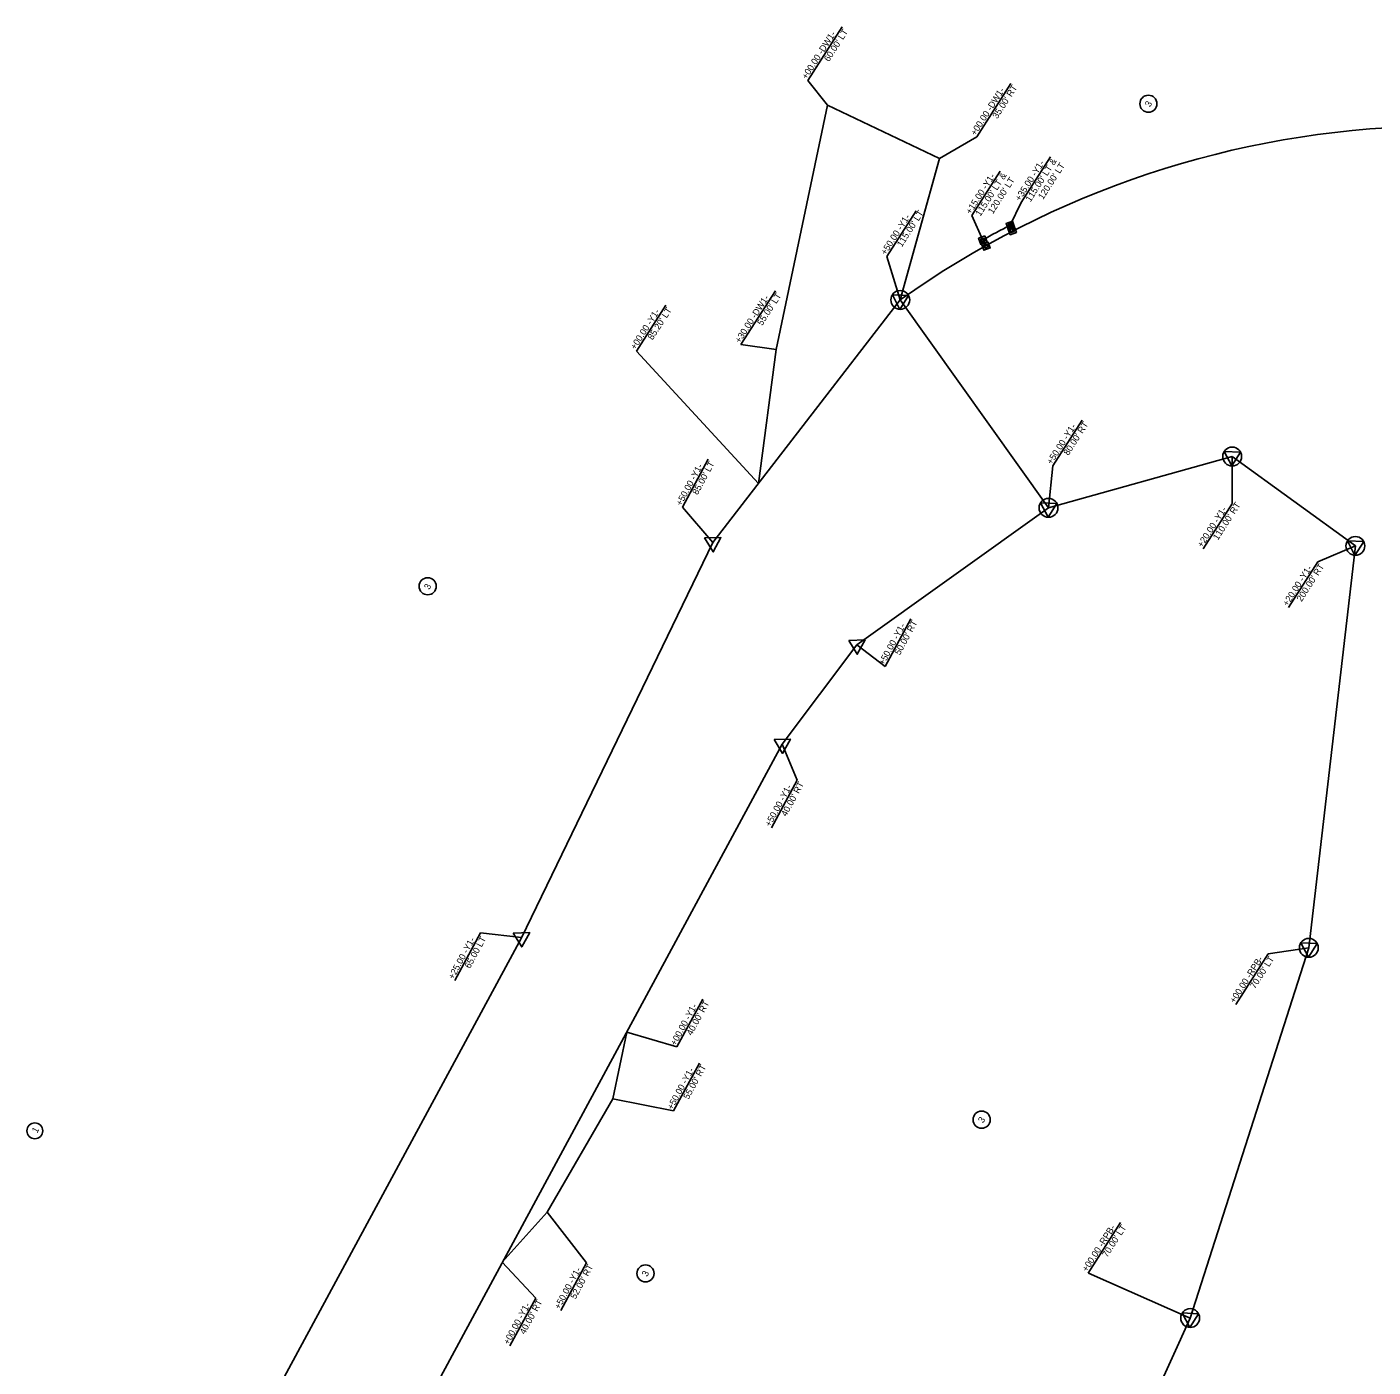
# Model space of a CAD drawing. Extents: x 2345854 to 2349056, y 842589 to 845145.
# Drawn here: x 2346489 to 2347518, y 843495 to 844519 of the extents above; entities that cross this region are included whole.
import ezdxf

# ---------------------------------------------------------------- set-up
doc = ezdxf.new("R2010")
doc.units = 0
for name, color, linetype in [('Prop Easement Construction', 7, 'Continuous'), ('Prop Easement Construction Station Offsets', 7, 'Continuous'), ('Prop Easement Permanent Drainage', 7, 'Continuous'), ('Prop Easement Permanent Drainage Station Offsets', 7, 'Continuous'), ('Prop Parcel Number Text', 7, 'Continuous'), ('Prop ROW CA Lines', 7, 'Continuous'), ('Prop ROW Marker CELL', 7, 'Continuous'), ('Prop ROW RW CA Lines', 7, 'Continuous'), ('Prop ROW RW Lines', 7, 'Continuous'), ('Prop ROW Station Offsets', 7, 'Continuous')]:
    doc.layers.add(name, color=color, linetype=linetype)

msp = doc.modelspace()

# ---------------------------------------------------------------- linework, layer by layer
at = {"layer": 'Prop Easement Construction'}
for p, q in [((2347061.7, 844272.8), (2347100.7, 844459.3)), ((2347100.7, 844459.3), (2347186.5, 844418.6)), ((2347156.4, 844310.6), (2347186.5, 844418.6)), ((2347048.1, 844170.5), (2347061.7, 844272.8)), ((2346936.9, 843700.3), (2346947.5, 843751.4)), ((2346886.7, 843613.8), (2346936.9, 843700.3)), ((2346852.4, 843575.5), (2346886.7, 843613.8))]:
    msp.add_line(p, q, dxfattribs=at)
at = {"layer": 'Prop Easement Construction Station Offsets'}
for p, q in [((2347112.1, 844519.2), (2347085.8, 844478.3)), ((2347241, 844476), (2347214.8, 844435.1)), ((2347061, 844317.5), (2347034.7, 844276.6)), ((2346977.3, 844306.6), (2346954.9, 844271.6)), ((2347005.5, 843776.5), (2346985.7, 843740)), ((2347003.1, 843727.6), (2346983.3, 843691.1)), ((2346916.8, 843575.1), (2346897, 843538.6)), ((2346877.9, 843548.1), (2346858.2, 843511.7))]:
    msp.add_line(p, q, dxfattribs=at)
for points in [[(2347085.8, 844478.3), (2347100.7, 844459.3)], [(2347214.8, 844435.1), (2347186.5, 844418.6)], [(2346954.9, 844271.6), (2347048.1, 844170.5)], [(2347034.7, 844276.6), (2347061.7, 844272.8)], [(2346985.7, 843740), (2346947.5, 843751.4)], [(2346983.3, 843691.1), (2346936.9, 843700.3)], [(2346916.8, 843575.1), (2346886.7, 843613.8)], [(2346877.9, 843548.1), (2346852.4, 843575.5)]]:
    msp.add_lwpolyline(points, dxfattribs=at)
at = {"layer": 'Prop Easement Permanent Drainage'}
for p, q in [((2347240.5, 844367.8), (2347242.8, 844363.4)), ((2347219.4, 844356.4), (2347221.8, 844352.1))]:
    msp.add_line(p, q, dxfattribs=at)
msp.add_arc((2347571.6, 843728.5), 720, 117.3799, 119.2898, dxfattribs=at)
at = {"layer": 'Prop Easement Permanent Drainage Station Offsets'}
for p, q in [((2347271.1, 844420), (2347248.7, 844385.1)), ((2347232.8, 844409), (2347211.1, 844375.1))]:
    msp.add_line(p, q, dxfattribs=at)
for points in [[(2347248.7, 844385.1), (2347240.5, 844367.8)], [(2347211.1, 844375.1), (2347219.4, 844356.4)]]:
    msp.add_lwpolyline(points, dxfattribs=at)
for points in [[(2347242.1, 844370.9), (2347243.8, 844366.1), (2347239, 844364.4), (2347237.3, 844369.1)], [(2347243.4, 844367), (2347245.2, 844362.2), (2347240.4, 844360.4), (2347238.7, 844365.2)], [(2347241.3, 844369.3), (2347242.2, 844366.9), (2347239.8, 844366), (2347238.9, 844368.4)], [(2347242.7, 844365.3), (2347243.5, 844362.9), (2347241.2, 844362.1), (2347240.3, 844364.5)], [(2347220.9, 844359.5), (2347222.7, 844354.7), (2347217.9, 844353), (2347216.2, 844357.8)], [(2347220.2, 844357.9), (2347221.1, 844355.5), (2347218.7, 844354.6), (2347217.8, 844357)], [(2347223.4, 844355.1), (2347225.1, 844350.4), (2347220.3, 844348.6), (2347218.6, 844353.4)], [(2347222.6, 844353.5), (2347223.5, 844351.1), (2347221.1, 844350.2), (2347220.2, 844352.6)]]:
    msp.add_lwpolyline(points, close=True, dxfattribs=at)
at = {"layer": 'Prop Parcel Number Text'}
for centre, radius in [((2347346, 844460.5), 6.54), ((2346795.4, 844091.9), 6.54), ((2347218.6, 843684.4), 6.54), ((2346495.3, 843675.9), 6.05), ((2346961.8, 843567), 6.54)]:
    msp.add_circle(centre, radius, dxfattribs=at)
at = {"layer": 'Prop ROW CA Lines'}
msp.add_line((2347269.7, 844151.8), (2347156.4, 844310.6), dxfattribs=at)
at = {"layer": 'Prop ROW Marker CELL'}
for p, q in [((2347240.5, 844367.6), (2347240.5, 844367.6)), ((2347241.9, 844363.7), (2347241.9, 844363.7)), ((2347219.4, 844356.2), (2347219.4, 844356.2)), ((2347221.9, 844351.9), (2347221.9, 844351.9)), ((2347156.4, 844310.6), (2347156.4, 844310.6)), ((2347410, 844191), (2347410, 844191)), ((2347269.7, 844151.8), (2347269.7, 844151.8)), ((2347013.3, 844125.3), (2347013.3, 844125.3)), ((2347504.1, 844122.7), (2347504.1, 844122.7)), ((2347123.3, 844047.1), (2347123.3, 844047.1)), ((2347066.3, 843971.4), (2347066.3, 843971.4)), ((2346867.1, 843823.6), (2346867.1, 843823.6)), ((2347468.5, 843815.7), (2347468.5, 843815.7)), ((2347377.9, 843532.9), (2347377.9, 843532.9))]:
    msp.add_line(p, q, dxfattribs=at)
for points in [[(2347156.1, 844303.4), (2347150.4, 844314.5), (2347162.8, 844313.9)], [(2347409.6, 844183.8), (2347403.9, 844194.9), (2347416.4, 844194.4)], [(2347269.3, 844144.6), (2347263.6, 844155.7), (2347276.1, 844155.1)], [(2347006.9, 844128.8), (2347019.4, 844129.1), (2347013.5, 844118.1)], [(2347503.8, 844115.5), (2347498.1, 844126.6), (2347510.5, 844126)], [(2347117, 844050.5), (2347129.5, 844050.9), (2347123.5, 844039.9)], [(2347060, 843974.8), (2347072.5, 843975.1), (2347066.5, 843964.2)], [(2346860.8, 843827), (2346873.3, 843827.3), (2346867.3, 843816.4)], [(2347468.2, 843808.5), (2347462.4, 843819.6), (2347474.9, 843819)], [(2347377.6, 843525.7), (2347371.8, 843536.8), (2347384.3, 843536.2)]]:
    msp.add_lwpolyline(points, close=True, dxfattribs=at)
for centre in [(2347156.4, 844310.6), (2347410, 844191), (2347269.7, 844151.8), (2347504.1, 844122.7), (2347468.5, 843815.7), (2347377.9, 843532.9)]:
    msp.add_circle(centre, 7.2, dxfattribs=at)
at = {"layer": 'Prop ROW RW CA Lines'}
for p, q in [((2347504.1, 844122.7), (2347410, 844191)), ((2347468.5, 843815.7), (2347504.1, 844122.7)), ((2347268.5, 843292.8), (2347377.9, 843532.9))]:
    msp.add_line(p, q, dxfattribs=at)
for points in [[(2347269.7, 844151.8), (2347410, 844191)], [(2347377.9, 843532.9), (2347468.5, 843815.7), (2347468.5, 843815.7)]]:
    msp.add_lwpolyline(points, dxfattribs=at)
msp.add_arc((2347571.6, 843728.5), 715, 91.3104, 125.4968, dxfattribs=at)
at = {"layer": 'Prop ROW RW Lines'}
for p, q in [((2346867, 843823.4), (2347013.3, 844125.3)), ((2346725.8, 843341.2), (2347066.3, 843971.4)), ((2346641.2, 843405.5), (2346867, 843823.4))]:
    msp.add_line(p, q, dxfattribs=at)
for points in [[(2347013.3, 844125.3), (2347156.4, 844310.6)], [(2347066.3, 843971.4), (2347123.3, 844047.1), (2347269.7, 844151.8)]]:
    msp.add_lwpolyline(points, dxfattribs=at)
at = {"layer": 'Prop ROW Station Offsets'}
for p, q in [((2347168.6, 844378.8), (2347146.2, 844343.9)), ((2347295.4, 844218.9), (2347273, 844184)), ((2347009.7, 844188.9), (2346990, 844152.4)), ((2347410.3, 844155.4), (2347387.9, 844120.5)), ((2347475.5, 844110.5), (2347453.1, 844075.6)), ((2347164.5, 844067.1), (2347144.8, 844030.6)), ((2347077.7, 843943.8), (2347058, 843907.3)), ((2346835.8, 843827.2), (2346816, 843790.7)), ((2347437.5, 843811), (2347412.8, 843772.4)), ((2347324.6, 843605.8), (2347299.9, 843567.2))]:
    msp.add_line(p, q, dxfattribs=at)
for points in [[(2347146.2, 844343.9), (2347156.4, 844310.6)], [(2347410.1, 844155.6), (2347410, 844191)], [(2347273, 844184), (2347269.7, 844151.8)], [(2346990, 844152.4), (2347013.3, 844125.3)], [(2347475.5, 844110.5), (2347504.1, 844122.7)], [(2347144.8, 844030.6), (2347123.3, 844047.1)], [(2347077.7, 843943.8), (2347066.3, 843971.4)], [(2346835.8, 843827.2), (2346867.1, 843823.6)], [(2347437.5, 843811), (2347468.5, 843815.7)], [(2347300.2, 843567.1), (2347377.9, 843532.9)]]:
    msp.add_lwpolyline(points, dxfattribs=at)

# ---------------------------------------------------------------- texts
at = {"layer": 'Prop Easement Construction Station Offsets'}
for s, rotation, p in [("60.00' LT", 57.3281, (2347101.9, 844492.2)), ('+00.00 -DW1-', 57.3281, (2347084.9, 844478.8)), ("35.00' RT", 57.3281, (2347230.6, 844448.6)), ('+00.00 -DW1-', 57.3281, (2347213.9, 844435.7)), ('+30.00 -DW1-', 57.3281, (2347033.9, 844277.2)), ("55.00' LT", 57.3281, (2347050.9, 844290.6)), ('+00.00 -Y1-', 57.3281, (2346954, 844272.2)), ("85.20' LT", 57.3281, (2346967.2, 844279.6)), ("40.00' RT", 61.6124, (2346997.1, 843748.3)), ('+00.00 -Y1-', 61.6124, (2346984.8, 843740.5)), ('+50.00 -Y1-', 61.6124, (2346982.4, 843691.6)), ("55.00' RT", 61.6124, (2346994.7, 843699.5)), ('+50.00 -Y1-', 61.6124, (2346896.1, 843539.1)), ("52.00' RT", 61.6124, (2346908.4, 843546.9)), ('+00.00 -Y1-', 61.6124, (2346857.3, 843512.1)), ("40.00' RT", 61.6124, (2346869.6, 843520))]:
    msp.add_text(s, height=5, rotation=rotation, dxfattribs=at).set_placement(p)
at = {"layer": 'Prop Easement Permanent Drainage Station Offsets'}
for s, p in [('+35.00 -Y1-', (2347247.9, 844385.7)), ("115.00' LT &", (2347255.9, 844385.1)), ("120.00' LT", (2347265.5, 844386.9)), ('+15.00 -Y1-', (2347210.2, 844375.7)), ("115.00' LT &", (2347217.6, 844374.1)), ("120.00' LT", (2347227.2, 844375.9))]:
    msp.add_text(s, height=5, rotation=57.3281, dxfattribs=at).set_placement(p)
at = {"layer": 'Prop Parcel Number Text'}
for s, rotation, p in [('3', 61.6124, (2347347.3, 844457.6)), ('3', 61.6124, (2346796.6, 844088.9)), ('3', 57.3281, (2347219.6, 843681.4)), ('1', 61.6124, (2346497, 843673.8)), ('3', 61.6124, (2346963, 843564.1))]:
    msp.add_text(s, height=5, rotation=rotation, dxfattribs=at).set_placement(p)
at = {"layer": 'Prop ROW Station Offsets'}
for s, rotation, p in [('+50.00 -Y1-', 57.3281, (2347145.3, 844344.5)), ("115.00' LT", 57.3281, (2347157.6, 844350.6)), ("80.00' RT", 57.3281, (2347284.9, 844191.4)), ('+50.00 -Y1-', 57.3281, (2347272.1, 844184.5)), ("85.00' LT", 61.6124, (2347001.6, 844161.3)), ('+50.00 -Y1-', 61.6124, (2346989.1, 844152.9)), ("110.00' RT", 57.3281, (2347399.1, 844126.7)), ('+20.00 -Y1-', 57.3281, (2347387.1, 844121.1)), ('+20.00 -Y1-', 57.3281, (2347452.3, 844076.2)), ("200.00' RT", 57.3281, (2347463, 844079.7)), ('+50.00 -Y1-', 61.6124, (2347143.9, 844031.1)), ("50.00' RT", 61.6124, (2347156.1, 844038.9)), ('+50.00 -Y1-', 61.6124, (2347057.1, 843907.8)), ("40.00' RT", 61.6124, (2347069.4, 843915.6)), ('+25.00 -Y1-', 61.6124, (2346815.1, 843791.2)), ('65.00 LT', 61.6124, (2346827.7, 843799.5)), ('+00.00 -RPB-', 57.3281, (2347411.9, 843773)), ("70.00' LT", 57.3281, (2347427.4, 843784)), ('+00.00 -RPB-', 57.3281, (2347299.1, 843567.8)), ("70.00' LT", 57.3281, (2347314.5, 843578.8))]:
    msp.add_text(s, height=5, rotation=rotation, dxfattribs=at).set_placement(p)

doc.saveas('drawing.dxf')
